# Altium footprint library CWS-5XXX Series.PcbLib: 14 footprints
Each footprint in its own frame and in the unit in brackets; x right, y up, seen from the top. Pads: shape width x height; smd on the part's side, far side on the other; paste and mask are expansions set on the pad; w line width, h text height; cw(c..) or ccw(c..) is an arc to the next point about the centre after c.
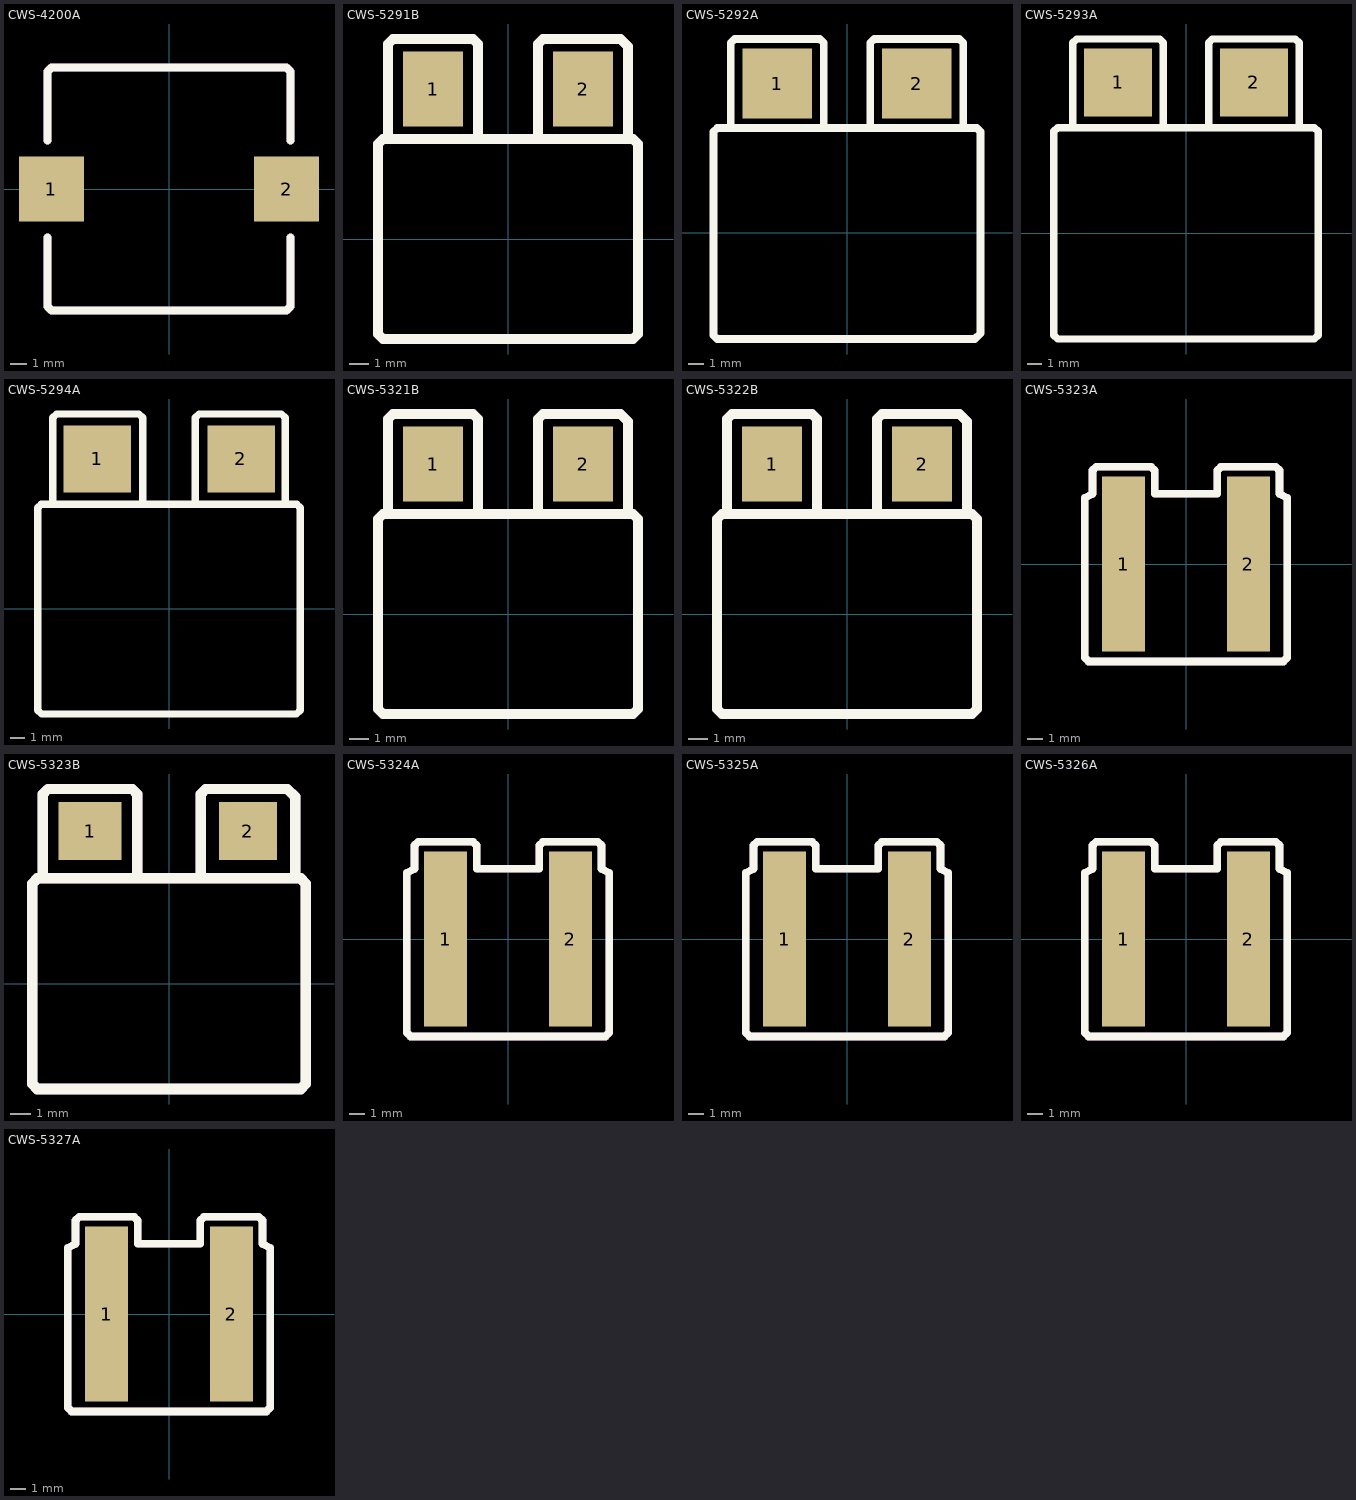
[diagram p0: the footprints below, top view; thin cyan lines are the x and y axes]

## CWS-4200A [mil]
pads (2):
  rect 160x160 smd: 1(-290,0) 2(290,0)
Top Overlay:
  lines w19.68: -300,290 -290,300 ; 290,300 300,290
  lines w20: -300,-120 -300,-290 -290,-300 290,-300 300,-290 300,-120 ; -300,120 -300,290 ; -290,300 290,300 ; 300,120 300,290
Mechanical 29:
  lines w19.68: -300,-120 -300,-290 -290,-300 290,-300 300,-290 300,-120 ; -300,120 -300,290 -290,300 290,300 300,290 300,120
  text "'.Designator'" at -850,-74.83 h400

## CWS-5291B [mil]
pads (2):
  rect 120x150 smd: 1(-150,300) 2(150,300)
Top Overlay:
  lines w19.68: -260,-190 -260,190 ; -240,200 -240,390 -230,400 -120,400 -70,400 -60,390 -60,200 ; 60,200 60,390 70,400 120,400 225,400 240,385 240,200 ; 260,-190 260,190
  lines w20: -260,-190 -250,-200 250,-200 260,-190 ; -260,190 -250,200 250,200 260,190
Mechanical 29:
  lines w19.68: -260,-190 -260,190 ; -240,200 -240,390 -230,400 -120,400 -70,400 -60,390 -60,200 ; 60,200 60,390 70,400 120,400 225,400 240,385 240,200 ; 260,-190 260,190
  lines w20: -260,-190 -250,-200 250,-200 260,-190 ; -260,190 -250,200 250,200 260,190
  text "'.Designator'" at -850,-74.83 h400

## CWS-5292A [mil]
pads (2):
  rect 180x180 smd: 1(-180,385) 2(180,385)
Top Overlay:
  lines w19.68: -335,270 -345,260 -345,-265 -335,-275 330,-275 345,-260 345,260 ; -300,270 -300,490 -290,500 -70,500 -60,490 -60,270 ; 60,270 60,490 70,500 290,500 300,490 300,275
  lines w20: -335,270 335,270 345,260
Mechanical 29:
  text "'.Designator'" at -845,-49.83 h400

## CWS-5293A [mil]
pads (2):
  rect 180x180 smd: 1(-180,400) 2(180,400)
Top Overlay:
  lines w19.68: -350,270 -350,-270 -340,-280 340,-280 350,-270 350,270 ; -300,280 -300,505 -290,515 -70,515 -60,505 -60,280 ; 60,280 60,505 70,515 290,515 300,505 300,280
  lines w20: -350,270 -340,280 340,280 350,270
Mechanical 29:
  text "'.Designator'" at -845,-49.83 h400

## CWS-5294A [mil]
pads (2):
  rect 180x180 smd: 1(-192,400) 2(192,400)
Top Overlay:
  lines w19.68: -350,270 -350,-270 -340,-280 340,-280 350,-270 350,270 ; -310,285 -310,510 -300,520 -80,520 -70,510 -70,285 ; 70,285 70,510 80,520 300,520 310,510 310,285
  lines w20: -350,270 -340,280 340,280 350,270
Mechanical 29:
  text "'.Designator'" at -845,-49.83 h400

## CWS-5321B [mil]
pads (2):
  rect 120x150 smd: 1(-150,300) 2(150,300)
Top Overlay:
  lines w19.68: -260,-190 -260,190 ; -240,200 -240,390 -230,400 -120,400 -70,400 -60,390 -60,200 ; 60,200 60,390 70,400 120,400 225,400 240,385 240,200 ; 260,-190 260,190
  lines w20: -260,-190 -250,-200 250,-200 260,-190 ; -260,190 -250,200 250,200 260,190
Mechanical 29:
  lines w19.68: -260,-190 -260,190 ; -240,200 -240,390 -230,400 -120,400 -70,400 -60,390 -60,200 ; 60,200 60,390 70,400 120,400 225,400 240,385 240,200 ; 260,-190 260,190
  lines w20: -260,-190 -250,-200 250,-200 260,-190 ; -260,190 -250,200 250,200 260,190
  text "'.Designator'" at -850,-74.83 h400

## CWS-5322B [mil]
pads (2):
  rect 120x150 smd: 1(-150,300) 2(150,300)
Top Overlay:
  lines w19.68: -260,-190 -260,190 ; -240,200 -240,390 -230,400 -120,400 -70,400 -60,390 -60,200 ; 60,200 60,390 70,400 120,400 225,400 240,385 240,200 ; 260,-190 260,190
  lines w20: -260,-190 -250,-200 250,-200 260,-190 ; -260,190 -250,200 250,200 260,190
Mechanical 29:
  lines w19.68: -260,-190 -260,190 ; -240,200 -240,390 -230,400 -120,400 -70,400 -60,390 -60,200 ; 60,200 60,390 70,400 120,400 225,400 240,385 240,200 ; 260,-190 260,190
  lines w20: -260,-190 -250,-200 250,-200 260,-190 ; -260,190 -250,200 250,200 260,190
  text "'.Designator'" at -850,-74.83 h400

## CWS-5323A [mil]
pads (2):
  rect 110x450 smd: 1(-160,0) 2(160,0)
Top Overlay:
  lines w19.68: -260,-240 -260,170 -240,180 -240,240 -230,250 -90,250 -80,240 -80,180 80,180 80,240 90,250 230,250 240,240 240,180 260,170 260,-240
  lines w20: -260,-240 -250,-250 250,-250 260,-240
Mechanical 29:
  lines w19.68: -260,-240 -260,170 -240,180 -240,240 -230,250 -90,250 -80,240 -80,180 80,180 80,240 90,250 230,250 240,240 240,180 260,170 260,-240
  lines w20: -260,-240 -250,-250 250,-250 260,-240
  text "'.Designator'" at -850,-74.83 h400

## CWS-5323B [mil]
pads (2):
  rect 120x110 smd: 1(-150,290)
  rect 110x110 smd: 2(150,290)
Top Overlay:
  lines w19.68: -260,-190 -260,190 ; -240,200 -240,360 -230,370 -120,370 -70,370 -60,360 -60,200 ; 60,200 60,360 70,370 120,370 225,370 240,355 240,200 ; 260,-190 260,190
  lines w20: -260,-190 -250,-200 250,-200 260,-190 ; -260,190 -250,200 250,200 260,190
Mechanical 29:
  lines w19.68: -260,-190 -260,190 ; -240,200 -240,360 -230,370 -120,370 -70,370 -60,360 -60,200 ; 60,200 60,360 70,370 120,370 225,370 240,355 240,200 ; 260,-190 260,190
  lines w20: -260,-190 -250,-200 250,-200 260,-190 ; -260,190 -250,200 250,200 260,190
  text "'.Designator'" at -850,-74.83 h400

## CWS-5324A [mil]
pads (2):
  rect 110x450 smd: 1(-160,0) 2(160,0)
Top Overlay:
  lines w19.68: -260,-240 -260,170 -240,180 -240,240 -230,250 -90,250 -80,240 -80,180 80,180 80,240 90,250 230,250 240,240 240,180 260,170 260,-240
  lines w20: -260,-240 -250,-250 250,-250 260,-240
Mechanical 29:
  lines w19.68: -260,-240 -260,170 -240,180 -240,240 -230,250 -90,250 -80,240 -80,180 80,180 80,240 90,250 230,250 240,240 240,180 260,170 260,-240
  lines w20: -260,-240 -250,-250 250,-250 260,-240
  text "'.Designator'" at -850,-74.83 h400

## CWS-5325A  [mil]
pads (2):
  rect 110x450 smd: 1(-160,0) 2(160,0)
Top Overlay:
  lines w19.68: -260,-240 -260,170 -240,180 -240,240 -230,250 -90,250 -80,240 -80,180 80,180 80,240 90,250 230,250 240,240 240,180 260,170 260,-240
  lines w20: -260,-240 -250,-250 250,-250 260,-240
Mechanical 29:
  lines w19.68: -260,-240 -260,170 -240,180 -240,240 -230,250 -90,250 -80,240 -80,180 80,180 80,240 90,250 230,250 240,240 240,180 260,170 260,-240
  lines w20: -260,-240 -250,-250 250,-250 260,-240
  text "'.Designator'" at -850,-74.83 h400

## CWS-5326A  [mil]
pads (2):
  rect 110x450 smd: 1(-160,0) 2(160,0)
Top Overlay:
  lines w19.68: -260,-240 -260,170 -240,180 -240,240 -230,250 -90,250 -80,240 -80,180 80,180 80,240 90,250 230,250 240,240 240,180 260,170 260,-240
  lines w20: -260,-240 -250,-250 250,-250 260,-240
Mechanical 29:
  lines w19.68: -260,-240 -260,170 -240,180 -240,240 -230,250 -90,250 -80,240 -80,180 80,180 80,240 90,250 230,250 240,240 240,180 260,170 260,-240
  lines w20: -260,-240 -250,-250 250,-250 260,-240
  text "'.Designator'" at -850,-74.83 h400

## CWS-5327A  [mil]
pads (2):
  rect 110x450 smd: 1(-160,0) 2(160,0)
Top Overlay:
  lines w19.68: -260,-240 -260,170 -240,180 -240,240 -230,250 -90,250 -80,240 -80,180 80,180 80,240 90,250 230,250 240,240 240,180 260,170 260,-240
  lines w20: -260,-240 -250,-250 250,-250 260,-240
Mechanical 29:
  lines w19.68: -260,-240 -260,170 -240,180 -240,240 -230,250 -90,250 -80,240 -80,180 80,180 80,240 90,250 230,250 240,240 240,180 260,170 260,-240
  lines w20: -260,-240 -250,-250 250,-250 260,-240
  text "'.Designator'" at -850,-74.83 h400

## PCBComponent_1 [mil]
